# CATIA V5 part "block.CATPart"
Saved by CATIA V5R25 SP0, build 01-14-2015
Part number: block
Bounding box of the stored display mesh (mm): x -30 to 30, y -25 to 8.5, z -53.5 to 85
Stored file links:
  C:\Users\feridun\Desktop\teksilindirlimotor\block.CATPart
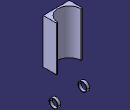
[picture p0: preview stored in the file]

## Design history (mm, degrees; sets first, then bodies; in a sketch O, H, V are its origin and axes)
Body1 (main body)
  Sketch1 on xy-plane, origin (0, 0, 0), H (1, 0, 0), V (0, 1, 0)
    arc A1 centre (0, 0) radius 22 from (22, 0) to (-22, 0) cw
    point P1 (-22, 0)
    line L1 (-22, 0) -> (-25, 0)
    line L2 (-25, 0) -> (-25, -25)
    line L3 (-25, -25) -> (25, -25)
    line L4 (25, -25) -> (25, 0)
    point P5 (25, 0)
    line L5 (25, 0) -> (22, 0)
    radius A1 = 22
    length L3 = 50
    length L2 = 25
    distance V L4 = 25
    coincidence: P1 H, P5 H
    horizontal: L1 H, L3 H, L5 H
    vertical: L2 V, L4 V
  Pad1: profile Sketch1, direction (0, 0, 1), length 85
  Sketch2 on face of Pad1 from Sketch1.L4, origin (25, 0, 0), H (0, 1, 0), V (0, 0, 1)
    circle A1 centre (0, -45) radius 7.5
    point P1 (0, -45)
    circle A2 centre (0, -45) radius 8.5
    radius A1 = 7.5
    radius A2 = 8.5
    distance H P1 = 45
    coincidence: P1 V
  Pad2: profile Sketch2, direction (1, 0, 0), length 5
  Mirror1: of the body so far, about yz-plane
